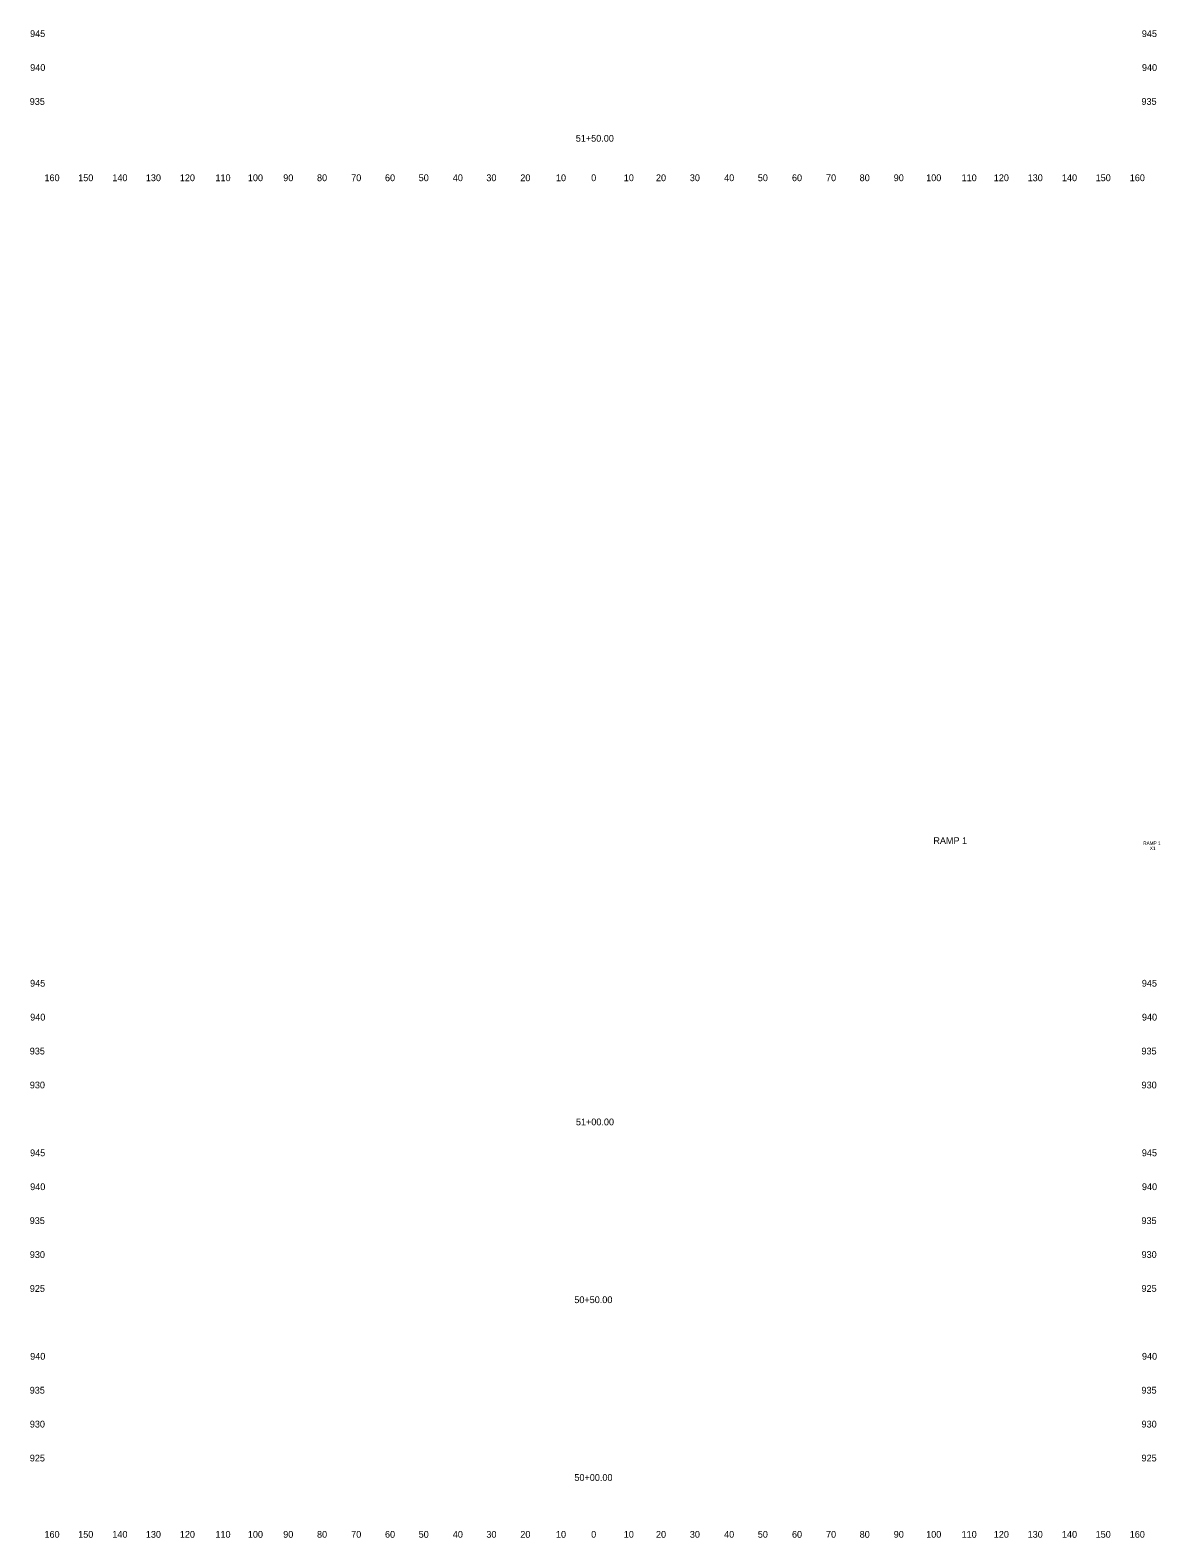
# Model space of a CAD drawing. Extents: x 4994 to 7869, y 4997 to 8804.
# Drawn here: x 4993.9 to 5327, y 4997.5 to 5442 of the extents above; entities that cross this region are included whole.
import ezdxf

# ---------------------------------------------------------------- set-up
doc = ezdxf.new("R2010")
doc.units = 0
for name, color, linetype in [('RD_SHT_ID', 7, 'Continuous'), ('RD_XS_TX_Offset', 7, 'Continuous'), ('RD_XS_TX_Station', 7, 'Continuous')]:
    doc.layers.add(name, color=color, linetype=linetype)

msp = doc.modelspace()

# ---------------------------------------------------------------- texts
at = {"layer": 'RD_SHT_ID'}
for s, height, p in [('RAMP 1', 2, (5260.19, 5202.06)), ('RAMP 1', 1, (5322.06, 5201.8)), ('X1', 1, (5324.02, 5200.3))]:
    msp.add_text(s, height=height, dxfattribs=at).set_placement(p)
at = {"layer": 'RD_XS_TX_Offset'}
for s, p in [('945', (4993.86, 5440)), ('945', (5321.66, 5440)), ('940', (4993.89, 5430)), ('940', (5321.69, 5430)), ('935', (4993.75, 5420)), ('935', (5321.55, 5420)), ('160', (4998.1, 5397.5)), ('150', (5008.04, 5397.5)), ('140', (5018.1, 5397.5)), ('130', (5027.99, 5397.5)), ('120', (5038.01, 5397.5)), ('110', (5048.51, 5397.5)), ('100', (5058.07, 5397.5)), ('90', (5068.5, 5397.5)), ('80', (5078.46, 5397.5)), ('70', (5088.54, 5397.5)), ('60', (5098.5, 5397.5)), ('50', (5108.43, 5397.5)), ('40', (5118.5, 5397.5)), ('30', (5128.39, 5397.5)), ('20', (5138.4, 5397.5)), ('10', (5148.91, 5397.5)), ('0', (5159.3, 5397.5)), ('0', (5159.3, 5397.5)), ('10', (5168.91, 5397.5)), ('20', (5178.4, 5397.5)), ('30', (5188.39, 5397.5)), ('40', (5198.5, 5397.5)), ('50', (5208.43, 5397.5)), ('60', (5218.5, 5397.5)), ('70', (5228.54, 5397.5)), ('80', (5238.46, 5397.5)), ('90', (5248.5, 5397.5)), ('100', (5258.07, 5397.5)), ('110', (5268.51, 5397.5)), ('120', (5278.01, 5397.5)), ('130', (5287.99, 5397.5)), ('140', (5298.1, 5397.5)), ('150', (5308.04, 5397.5)), ('160', (5318.1, 5397.5)), ('945', (4993.86, 5160)), ('945', (5321.66, 5160)), ('940', (4993.89, 5150)), ('940', (5321.69, 5150)), ('935', (4993.75, 5140)), ('935', (5321.55, 5140)), ('930', (4993.78, 5130)), ('930', (5321.58, 5130)), ('945', (4993.86, 5110)), ('945', (5321.66, 5110)), ('940', (4993.89, 5100)), ('940', (5321.69, 5100)), ('935', (4993.75, 5090)), ('935', (5321.55, 5090)), ('930', (4993.78, 5080)), ('930', (5321.58, 5080)), ('925', (4993.77, 5070)), ('925', (5321.57, 5070)), ('940', (4993.89, 5050)), ('940', (5321.69, 5050)), ('935', (4993.75, 5040)), ('935', (5321.55, 5040)), ('930', (4993.78, 5030)), ('930', (5321.58, 5030)), ('925', (4993.77, 5020)), ('925', (5321.57, 5020)), ('160', (4998.1, 4997.5)), ('150', (5008.04, 4997.5)), ('140', (5018.1, 4997.5)), ('130', (5027.99, 4997.5)), ('120', (5038.01, 4997.5)), ('110', (5048.51, 4997.5)), ('100', (5058.07, 4997.5)), ('90', (5068.5, 4997.5)), ('80', (5078.46, 4997.5)), ('70', (5088.54, 4997.5)), ('60', (5098.5, 4997.5)), ('50', (5108.43, 4997.5)), ('40', (5118.5, 4997.5)), ('30', (5128.39, 4997.5)), ('20', (5138.4, 4997.5)), ('10', (5148.91, 4997.5)), ('0', (5159.3, 4997.5)), ('0', (5159.3, 4997.5)), ('10', (5168.91, 4997.5)), ('20', (5178.4, 4997.5)), ('30', (5188.39, 4997.5)), ('40', (5198.5, 4997.5)), ('50', (5208.43, 4997.5)), ('60', (5218.5, 4997.5)), ('70', (5228.54, 4997.5)), ('80', (5238.46, 4997.5)), ('90', (5248.5, 4997.5)), ('100', (5258.07, 4997.5)), ('110', (5268.51, 4997.5)), ('120', (5278.01, 4997.5)), ('130', (5287.99, 4997.5)), ('140', (5298.1, 4997.5)), ('150', (5308.04, 4997.5)), ('160', (5318.1, 4997.5))]:
    msp.add_text(s, height=2, dxfattribs=at).set_placement(p)
at = {"layer": 'RD_XS_TX_Station'}
for s, p in [('51+50.00', (5154.76, 5409.14)), ('51+00.00', (5154.8, 5119.11)), ('50+50.00', (5154.32, 5066.68)), ('50+00.00', (5154.35, 5014.26))]:
    msp.add_text(s, height=2, dxfattribs=at).set_placement(p)

doc.saveas('drawing.dxf')
